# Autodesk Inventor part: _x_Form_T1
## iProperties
Created: 2005-11
Part Number: _x_Form_T1
Document SubType Name: Modeling
Designer: IMA/Frank
Manufacturer: Standard
Standards Organization: Custom
Author: IMA/Frank
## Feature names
1. Trennen1
2. Abgeleiteter Körper1 [Tagging]
